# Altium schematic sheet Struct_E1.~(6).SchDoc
size 420 x 297 mm; Scale: 1:1; Разраб.: Иванов; Обозначение документа: АБВГ.123456.001 Э3; Пров.: Петров; Утв.: Сидоров; Наименование организации: ОАО "Концерн "МПО-Гидроприбор"; Перв. применение: АБВГ.123456.000; Наименование изделия 1: Плата; Наименование изделия 2: Схема электрическая; Наименование изделия 3: принципиальная; Нач. отд.: Нач. отд.; Фамилия нач. отд.: Сидоров
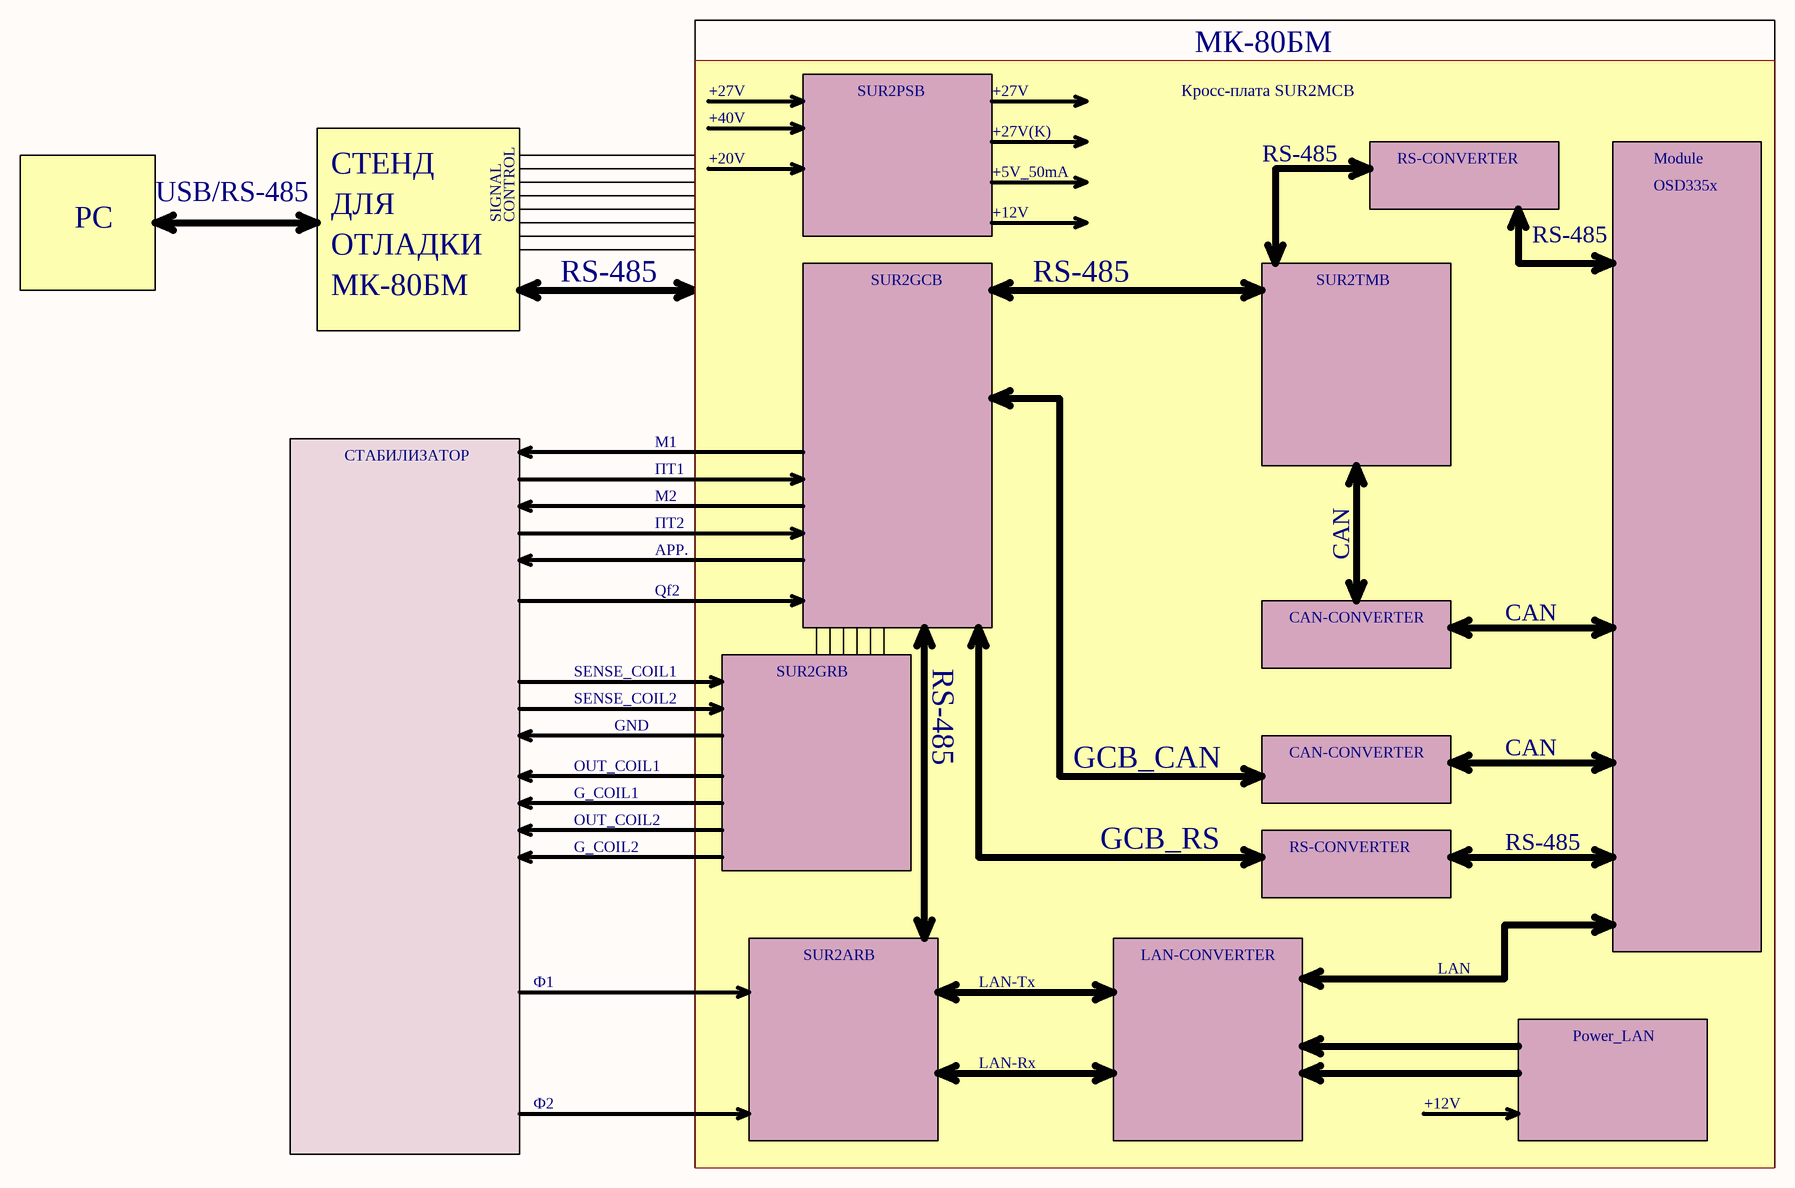
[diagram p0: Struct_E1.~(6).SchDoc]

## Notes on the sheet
- +27V
- SUR2PSB
- Кросс-плата SUR2MCB
- МК-80БМ
- СТЕНД
- +40V
- +20V
- +27V(K)
- +5V_50mA
- RS-485
- RS-CONVERTER
- Module
- PC
- USB/RS-485
- ДЛЯ
- SIGNAL
- CONTROL
- +12V
- OSD335x
- ОТЛАДКИ
- SUR2GCB
- SUR2TMB
- M1
- СТАБИЛИЗАТОР
- M2
- ПТ1
- ПТ2
- АРР.
- CAN
- Qf2
- CAN-CONVERTER
- SENSE_COIL1
- SENSE_COIL2
- SUR2GRB
- OUT_COIL1
- GND
- GCB_CAN
- OUT_COIL2
- G_COIL1
- G_COIL2
- GCB_RS
- Ф1
- SUR2ARB
- LAN-Tx
- LAN-CONVERTER
- LAN
- Power_LAN
- Ф2
- LAN-Rx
